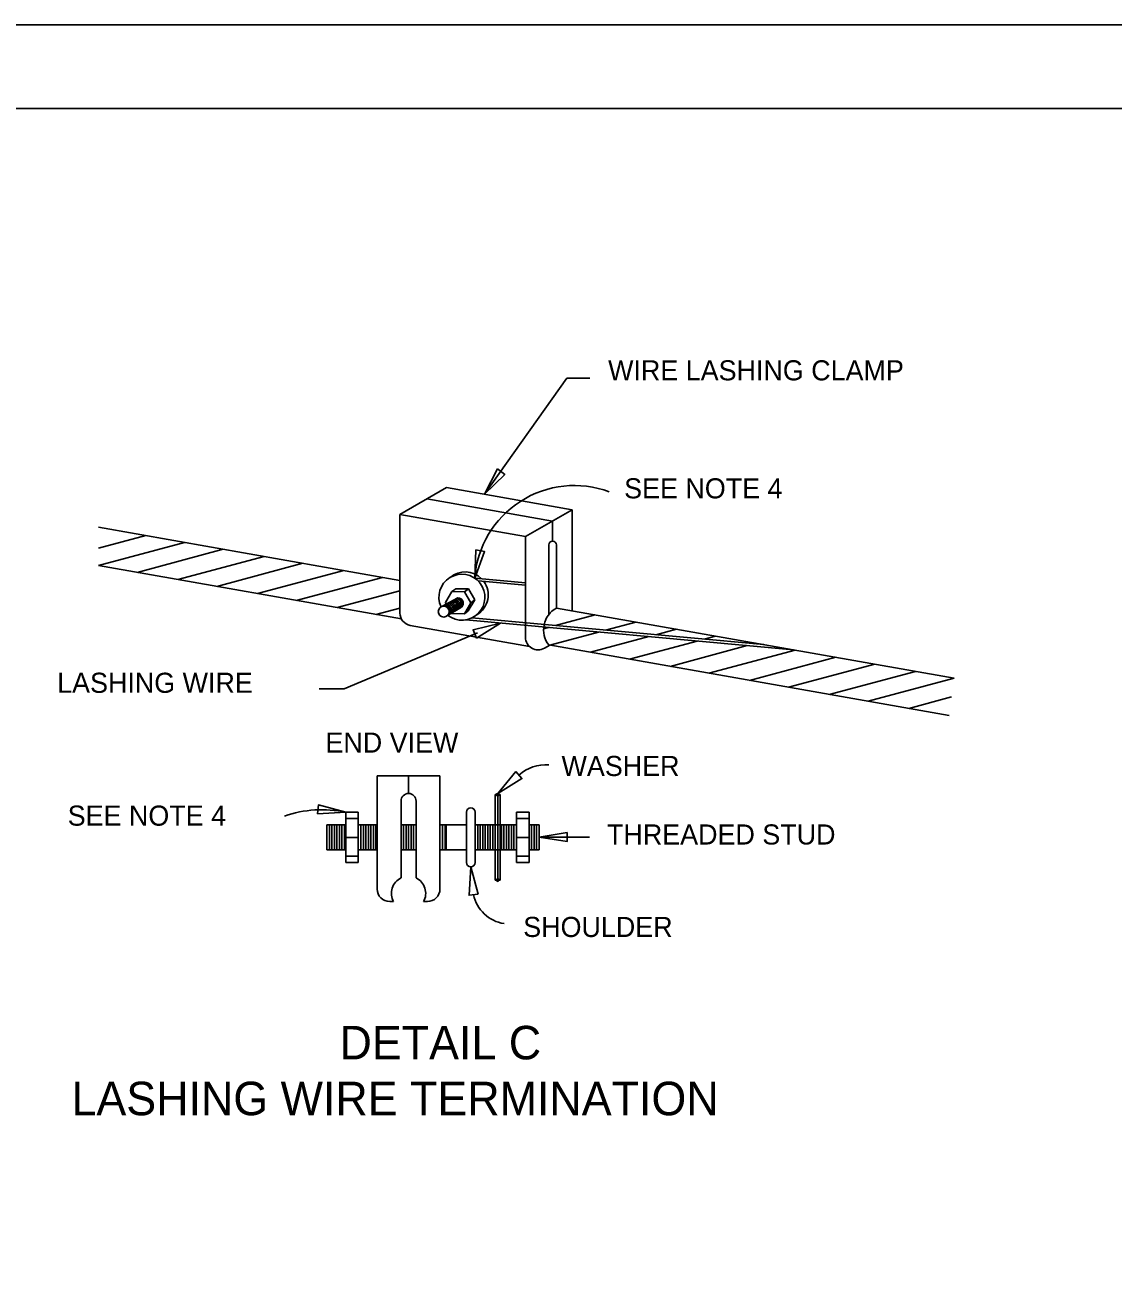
# Model space of a CAD drawing. Extents: x 1299104.8 to 1299141.6, y 239639.8 to 239661.8.
# Drawn here: x 1299120.32 to 1299126.82, y 239654.39 to 239661.79 of the extents above; entities that cross this region are included whole.
import ezdxf

# ---------------------------------------------------------------- set-up
doc = ezdxf.new("R2010")
doc.units = 0
for name, color, linetype in [('DIM TXT', 7, 'Continuous'), ('GS_plotshape_p', 7, 'Continuous'), ('Level 1', 7, 'Continuous')]:
    doc.layers.add(name, color=color, linetype=linetype)

msp = doc.modelspace()

# ---------------------------------------------------------------- linework, layer by layer
at = {"layer": 'DIM TXT'}
for p, q in [((1299123.5594, 239659.6829), (1299123.0677, 239658.9894)), ((1299123.6956, 239659.6829), (1299123.5594, 239659.6829)), ((1299122.8405, 239659.0295), (1299122.562, 239658.8687)), ((1299122.8405, 239659.0295), (1299123.5905, 239658.8973)), ((1299122.7237, 239658.9621), (1299123.4737, 239658.8298)), ((1299123.5905, 239658.8973), (1299123.312, 239658.7365)), ((1299123.5905, 239658.8973), (1299123.5905, 239658.2939)), ((1299122.562, 239658.8687), (1299123.312, 239658.7365)), ((1299122.562, 239658.8687), (1299122.562, 239658.2805)), ((1299123.4737, 239658.8298), (1299123.4737, 239658.7098)), ((1299120.762, 239658.7926), (1299122.562, 239658.4752)), ((1299121.045, 239658.7427), (1299120.762, 239658.6669)), ((1299121.2763, 239658.7019), (1299120.762, 239658.5641)), ((1299123.312, 239658.7365), (1299123.312, 239658.1353)), ((1299123.4512, 239658.6873), (1299123.4512, 239658.2722)), ((1299123.4962, 239658.6873), (1299123.4962, 239658.3105)), ((1299121.5075, 239658.6611), (1299120.9933, 239658.5234)), ((1299121.7515, 239658.6181), (1299121.2372, 239658.4803)), ((1299120.762, 239658.5641), (1299122.5709, 239658.2452)), ((1299121.9827, 239658.5774), (1299121.4684, 239658.4396)), ((1299122.2266, 239658.5343), (1299121.7124, 239658.3965)), ((1299122.4579, 239658.4936), (1299121.9436, 239658.3558)), ((1299123.0088, 239658.4893), (1299123.312, 239658.4616)), ((1299123.0295, 239658.4723), (1299123.312, 239658.4465)), ((1299122.562, 239658.4131), (1299122.1876, 239658.3128)), ((1299122.8722, 239658.4081), (1299122.8952, 239658.4249)), ((1299122.948, 239658.4077), (1299122.971, 239658.4246)), ((1299122.562, 239658.3104), (1299122.4188, 239658.272)), ((1299122.9072, 239658.3719), (1299122.813, 239658.3201)), ((1299122.9195, 239658.309), (1299122.847, 239658.2663)), ((1299122.9855, 239658.3419), (1299123.0086, 239658.3588)), ((1299123.4962, 239658.3105), (1299125.8718, 239657.8916)), ((1299122.9473, 239658.2765), (1299122.9704, 239658.2933)), ((1299122.9557, 239658.2396), (1299124.912, 239658.0608)), ((1299122.9923, 239658.2513), (1299124.7347, 239658.0921)), ((1299123.7284, 239658.2695), (1299123.4904, 239658.2058)), ((1299123.0251, 239658.1626), (1299122.2293, 239657.8287)), ((1299122.624, 239658.2066), (1299123.335, 239658.0813)), ((1299123.4485, 239658.1945), (1299123.4199, 239658.1869)), ((1299123.7485, 239658.1671), (1299123.4568, 239658.089)), ((1299123.971, 239658.2268), (1299123.7904, 239658.1784)), ((1299124.2136, 239658.184), (1299124.0904, 239658.151)), ((1299123.4245, 239658.0703), (1299123.4568, 239658.089)), ((1299123.4512, 239658.09), (1299125.8405, 239657.6687)), ((1299124.0485, 239658.1397), (1299123.6994, 239658.0462)), ((1299124.3361, 239658.1135), (1299123.932, 239658.0052)), ((1299124.6361, 239658.0861), (1299124.1746, 239657.9624)), ((1299124.4462, 239658.143), (1299124.378, 239658.1247)), ((1299124.6888, 239658.1002), (1299124.678, 239658.0973)), ((1299124.9214, 239658.0592), (1299124.4071, 239657.9214)), ((1299125.164, 239658.0164), (1299124.6498, 239657.8786)), ((1299125.3966, 239657.9754), (1299124.8823, 239657.8376)), ((1299125.6392, 239657.9326), (1299125.1249, 239657.7948)), ((1299125.8718, 239657.8916), (1299125.3575, 239657.7538)), ((1299122.2293, 239657.8287), (1299122.0793, 239657.8287)), ((1299125.856, 239657.7796), (1299125.6001, 239657.711)), ((1299122.4263, 239657.3085), (1299122.4263, 239656.6335)), ((1299122.4263, 239657.3085), (1299122.8013, 239657.3085)), ((1299122.6138, 239657.3085), (1299122.6138, 239657.2035)), ((1299122.8013, 239657.3085), (1299122.8013, 239656.6335)), ((1299123.1313, 239657.1967), (1299123.1313, 239656.6867)), ((1299123.1313, 239657.1967), (1299123.1613, 239657.1967)), ((1299123.1613, 239657.1967), (1299123.1613, 239656.6867)), ((1299122.5688, 239657.1585), (1299122.5688, 239656.6993)), ((1299122.6588, 239657.1585), (1299122.6588, 239656.6993)), ((1299122.2388, 239657.0917), (1299122.2388, 239656.7917)), ((1299122.2388, 239657.0917), (1299122.3138, 239657.0917)), ((1299122.2388, 239657.0542), (1299122.3138, 239657.0542)), ((1299122.3138, 239657.0917), (1299122.3138, 239656.7917)), ((1299122.9588, 239657.0917), (1299122.9588, 239656.7917)), ((1299123.0113, 239657.0917), (1299123.0113, 239656.7917)), ((1299123.2582, 239657.0917), (1299123.2582, 239656.7917)), ((1299123.2582, 239657.0917), (1299123.3332, 239657.0917)), ((1299123.2582, 239657.0542), (1299123.3332, 239657.0542)), ((1299123.3332, 239657.0917), (1299123.3332, 239656.7917)), ((1299122.1263, 239657.0167), (1299122.1263, 239656.8667)), ((1299122.1263, 239657.0167), (1299122.2388, 239657.0167)), ((1299122.1413, 239657.0167), (1299122.1413, 239656.8667)), ((1299122.1563, 239657.0167), (1299122.1563, 239656.8667)), ((1299122.1713, 239657.0167), (1299122.1713, 239656.8667)), ((1299122.1863, 239657.0167), (1299122.1863, 239656.8667)), ((1299122.2013, 239657.0167), (1299122.2013, 239656.8667)), ((1299122.2163, 239657.0167), (1299122.2163, 239656.8667)), ((1299122.2313, 239657.0167), (1299122.2313, 239656.8667)), ((1299122.3138, 239657.0167), (1299122.4263, 239657.0167)), ((1299122.3288, 239657.0167), (1299122.3288, 239656.8667)), ((1299122.3438, 239657.0167), (1299122.3438, 239656.8667)), ((1299122.3588, 239657.0167), (1299122.3588, 239656.8667)), ((1299122.3738, 239657.0167), (1299122.3738, 239656.8667)), ((1299122.3888, 239657.0167), (1299122.3888, 239656.8667)), ((1299122.4038, 239657.0167), (1299122.4038, 239656.8667)), ((1299122.4188, 239657.0167), (1299122.4188, 239656.8667)), ((1299122.5688, 239657.0167), (1299122.6588, 239657.0167)), ((1299122.5838, 239657.0167), (1299122.5838, 239656.8667)), ((1299122.5988, 239657.0167), (1299122.5988, 239656.8667)), ((1299122.6138, 239657.0167), (1299122.6138, 239656.8667)), ((1299122.6288, 239657.0167), (1299122.6288, 239656.8667)), ((1299122.6438, 239657.0167), (1299122.6438, 239656.8667)), ((1299122.8013, 239657.0167), (1299122.9588, 239657.0167)), ((1299122.8163, 239657.0167), (1299122.8163, 239656.8667)), ((1299122.8313, 239657.0167), (1299122.8313, 239656.8667)), ((1299122.8388, 239657.0167), (1299122.8388, 239656.8667)), ((1299123.0113, 239657.0167), (1299123.2582, 239657.0167)), ((1299123.0263, 239657.0167), (1299123.0263, 239656.8667)), ((1299123.0413, 239657.0167), (1299123.0413, 239656.8667)), ((1299123.0563, 239657.0167), (1299123.0563, 239656.8667)), ((1299123.0713, 239657.0167), (1299123.0713, 239656.8667)), ((1299123.0863, 239657.0167), (1299123.0863, 239656.8667)), ((1299123.1013, 239657.0167), (1299123.1013, 239656.8667)), ((1299123.1163, 239657.0167), (1299123.1163, 239656.8667)), ((1299123.1682, 239657.0167), (1299123.1682, 239656.8667)), ((1299123.1832, 239657.0167), (1299123.1832, 239656.8667)), ((1299123.1982, 239657.0167), (1299123.1982, 239656.8667)), ((1299123.2132, 239657.0167), (1299123.2132, 239656.8667)), ((1299123.2282, 239657.0167), (1299123.2282, 239656.8667)), ((1299123.2432, 239657.0167), (1299123.2432, 239656.8667)), ((1299123.3332, 239657.0167), (1299123.3933, 239657.0167)), ((1299123.3483, 239657.0167), (1299123.3483, 239656.8667)), ((1299123.3633, 239657.0167), (1299123.3633, 239656.8667)), ((1299123.3783, 239657.0167), (1299123.3783, 239656.8667)), ((1299123.3933, 239657.0167), (1299123.3933, 239656.8667)), ((1299122.2388, 239656.9417), (1299122.3138, 239656.9417)), ((1299123.2582, 239656.9417), (1299123.3332, 239656.9417)), ((1299123.6931, 239656.9437), (1299123.3933, 239656.9437)), ((1299122.1263, 239656.8667), (1299122.2388, 239656.8667)), ((1299122.2388, 239656.8292), (1299122.3138, 239656.8292)), ((1299122.3138, 239656.8667), (1299122.4263, 239656.8667)), ((1299122.5688, 239656.8667), (1299122.6588, 239656.8667)), ((1299122.8013, 239656.8667), (1299122.9588, 239656.8667)), ((1299123.0113, 239656.8667), (1299123.2582, 239656.8667)), ((1299123.2582, 239656.8292), (1299123.3332, 239656.8292)), ((1299123.3332, 239656.8667), (1299123.3933, 239656.8667)), ((1299122.2388, 239656.7917), (1299122.3138, 239656.7917)), ((1299123.2582, 239656.7917), (1299123.3332, 239656.7917)), ((1299123.1313, 239656.6867), (1299123.1613, 239656.6867)), ((1299122.5013, 239656.5585), (1299122.5243, 239656.5585)), ((1299122.7032, 239656.5585), (1299122.7263, 239656.5585))]:
    msp.add_line(p, q, dxfattribs=at)
for points in [[(1299123.1442, 239659.1402), (1299123.1881, 239659.1081), (1299123.0677, 239658.9894)], [(1299123.0146, 239658.6582), (1299123.0679, 239658.6477), (1299123.0088, 239658.4893)], [(1299123.0201, 239658.1309), (1299122.9991, 239658.181), (1299123.1634, 239658.2206)], [(1299123.2544, 239657.3341), (1299123.2901, 239657.293), (1299123.1463, 239657.2042)], [(1299122.07, 239657.0815), (1299122.0755, 239657.1355), (1299122.2388, 239657.0917)], [(1299123.5601, 239656.971), (1299123.5602, 239656.9166), (1299123.3933, 239656.9437)], [(1299123.029, 239656.6022), (1299122.9749, 239656.5967), (1299122.985, 239656.7654)]]:
    msp.add_lwpolyline(points, close=True, dxfattribs=at)
for points in [[(1299122.8722, 239658.4081), (1299122.834, 239658.3426), (1299122.8388, 239658.3343)], [(1299122.9855, 239658.3419), (1299122.948, 239658.4077), (1299122.8722, 239658.4081)], [(1299123.0086, 239658.3588), (1299122.971, 239658.4246), (1299122.8952, 239658.4249)], [(1299122.8699, 239658.2798), (1299122.8716, 239658.2768), (1299122.9473, 239658.2765), (1299122.9855, 239658.3419)], [(1299122.9704, 239658.2933), (1299123.0086, 239658.3588)], [(1299123.1463, 239656.6867), (1299123.1463, 239657.1967)]]:
    msp.add_lwpolyline(points, dxfattribs=at)
msp.add_circle((1299122.8237, 239658.2892), 0.0327, dxfattribs=at)
for centre, radius, start, end in [((1299123.6041, 239658.4445), 0.597, 69.64878, 175.6975), ((1299123.4737, 239658.6873), 0.0225, 0, 180), ((1299122.9517, 239658.3889), 0.1374, 44.71121, 130.62193), ((1299122.9324, 239658.375), 0.1374, 231.96344, 204.68941), ((1299122.9517, 239658.3889), 0.1374, 300.7009, 35.78623), ((1299122.8307, 239658.293), 0.0327, 317.67748, 110.30149), ((1299122.8386, 239658.2971), 0.0327, 320.11389, 125.45501), ((1299122.8474, 239658.3028), 0.0327, 317.67748, 105.20331), ((1299122.8553, 239658.3069), 0.0327, 320.11389, 106.64225), ((1299122.8641, 239658.3121), 0.0327, 320.11389, 104.40682), ((1299122.8729, 239658.3178), 0.0327, 317.67748, 99.87638), ((1299122.8808, 239658.3219), 0.0327, 320.11389, 100.89222), ((1299122.8887, 239658.3266), 0.0327, 320.11389, 99.43976), ((1299122.8976, 239658.3323), 0.0327, 317.67748, 95.84081), ((1299122.9054, 239658.3364), 0.0327, 330.99919, 96.67822), ((1299122.9072, 239658.3393), 0.0327, 292.12918, 90), ((1299123.5675, 239658.1811), 0.1478, 118.86478, 218.06967), ((1299122.637, 239658.2805), 0.075, 180, 260), ((1299123.387, 239658.1353), 0.075, 180, 300), ((1299123.4322, 239657.135), 0.2397, 85.26855, 131.84793), ((1299122.6138, 239657.1585), 0.045, 0, 180), ((1299123.1463, 239657.1967), 0.0075, 0, 180), ((1299123.1463, 239657.1967), 0.0075, 180, 0), ((1299122.985, 239657.0917), 0.0262, 0, 180), ((1299122.0962, 239656.4269), 0.6799, 77.89755, 109.24033), ((1299122.985, 239656.7917), 0.0262, 180, 0), ((1299122.6138, 239656.6077), 0.1021, 116.16484, 208.81486), ((1299122.6138, 239656.6077), 0.1021, 331.18514, 63.83516), ((1299123.1463, 239656.6867), 0.0075, 0, 180), ((1299123.1463, 239656.6867), 0.0075, 180, 0), ((1299122.5013, 239656.6335), 0.075, 180, 270), ((1299122.7263, 239656.6335), 0.075, 270, 0), ((1299123.2163, 239656.6437), 0.2189, 191.66476, 261.55048)]:
    msp.add_arc(centre, radius, start, end, dxfattribs=at)
at = {"layer": 'GS_plotshape_p'}
msp.add_lwpolyline([(1299104.8019, 239661.7913), (1299138.8019, 239661.7913), (1299138.8019, 239639.7913), (1299104.8019, 239639.7913)], close=True, dxfattribs=at)
at = {"layer": 'Level 1'}
msp.add_lwpolyline([(1299138.3019, 239640.2913), (1299106.3019, 239640.2913), (1299106.3019, 239661.2913), (1299138.3019, 239661.2913)], close=True, dxfattribs=at)

# ---------------------------------------------------------------- texts
at = {"layer": 'DIM TXT'}
for s, height, p in [('WIRE LASHING CLAMP', 0.12, (1299123.805, 239659.6691)), ('SEE NOTE 4', 0.12, (1299123.9008, 239658.9648)), ('LASHING WIRE', 0.12, (1299120.5159, 239657.8043)), ('END VIEW', 0.12, (1299122.1176, 239657.4475)), ('WASHER', 0.12, (1299123.527, 239657.3077)), ('SEE NOTE 4', 0.12, (1299120.5788, 239657.0114)), ('THREADED STUD', 0.12, (1299123.7985, 239656.899)), ('SHOULDER', 0.12, (1299123.2984, 239656.3471)), ('DETAIL C', 0.2, (1299122.2015, 239655.6167)), ('LASHING WIRE TERMINATION', 0.2, (1299120.6015, 239655.2833))]:
    msp.add_text(s, height=height, dxfattribs=at).set_placement(p)

doc.saveas('drawing.dxf')
